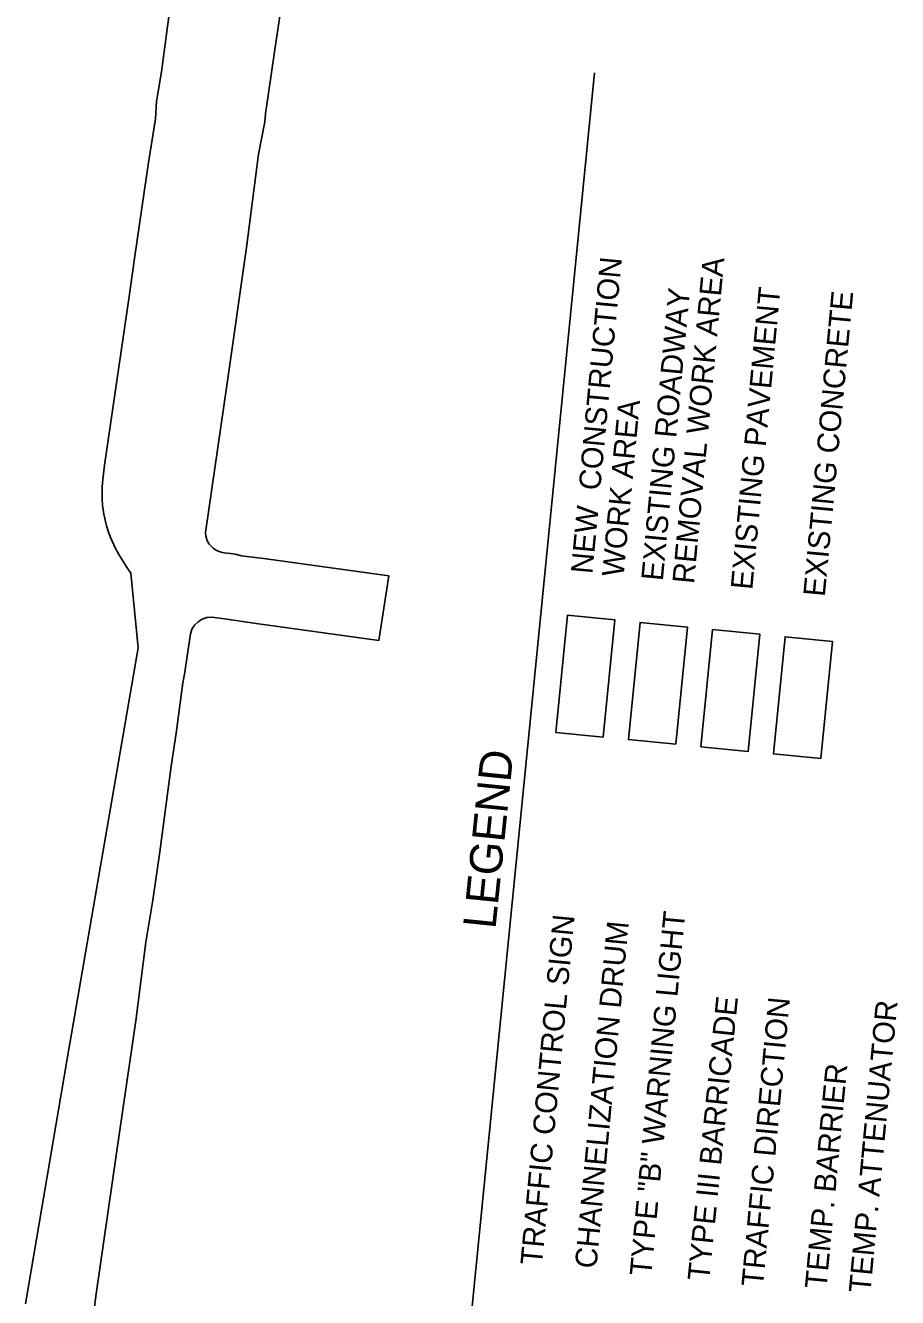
# Model space of a CAD drawing. Extents: x 1795987 to 1799689, y 243690 to 251545.
# Drawn here: x 1797696 to 1798009.1, y 245992.6 to 246449.6 of the extents above; entities that cross this region are included whole.
import ezdxf

# ---------------------------------------------------------------- set-up
doc = ezdxf.new("R2010")
doc.units = 0
doc.layers.add('LEGEND', color=7, linetype='Continuous')
doc.layers.add('Level 62', color=7, linetype='Continuous')

msp = doc.modelspace()

# ---------------------------------------------------------------- linework, layer by layer
at = {"layer": 'LEGEND'}
msp.add_line((1797853.4, 245958.82), (1797900.34, 246432.57), dxfattribs=at)
for points in [[(1797903.46, 246193.96), (1797907.63, 246236.03), (1797890.65, 246237.71), (1797886.48, 246195.64)], [(1797929.5, 246191.38), (1797933.67, 246233.45), (1797916.68, 246235.13), (1797912.51, 246193.06)], [(1797955.54, 246188.8), (1797959.71, 246230.87), (1797942.72, 246232.55), (1797938.55, 246190.48)], [(1797981.58, 246186.22), (1797985.74, 246228.29), (1797968.76, 246229.97), (1797964.59, 246187.9)]]:
    msp.add_lwpolyline(points, close=True, dxfattribs=at)
at = {"layer": 'Level 62'}
msp.add_line((1797826.51, 246251.82), (1797822.87, 246228.68), dxfattribs=at)
for points in [[(1797719.43, 245978.94), (1797721.41, 245993.91), (1797728.54, 246043.6), (1797730.99, 246060.2), (1797735.63, 246091.99), (1797739.24, 246120.33), (1797741.69, 246135.32), (1797744.16, 246152.76), (1797748.27, 246183.48), (1797750.08, 246195.31), (1797752.47, 246213.38), (1797753.02, 246216.51), (1797755.18, 246231), (1797755.75, 246232.66), (1797756.69, 246234.15), (1797757.94, 246235.38), (1797759.44, 246236.31), (1797761.1, 246236.87), (1797762.85, 246237.05), (1797767.42, 246236.38), (1797778.78, 246234.79), (1797822.87, 246228.68), (1797826.51, 246251.82), (1797782.39, 246257.94), (1797773.6, 246259.09), (1797771.33, 246259.63), (1797769.55, 246259.9), (1797767.29, 246260.12), (1797766.19, 246260.36), (1797764.62, 246261.01), (1797763.34, 246261.86), (1797761.99, 246263.23), (1797761.22, 246264.46), (1797760.7, 246266.2), (1797760.65, 246267.37), (1797768.4, 246321.08), (1797775.39, 246369.77), (1797779.65, 246403.28), (1797781.87, 246414.95), (1797782.15, 246417.96), (1797783.16, 246424.45), (1797785.46, 246440.9), (1797790.89, 246476.94)], [(1797750.05, 246471.73), (1797746.95, 246449.21), (1797744.84, 246432.9), (1797743.57, 246425.8), (1797743.06, 246422.22), (1797742.71, 246416.04), (1797740.14, 246400.35), (1797735.26, 246366.63), (1797733.04, 246351.32), (1797724.36, 246291.61), (1797723.7, 246286.42), (1797723.5, 246283.83), (1797723.5, 246279.46), (1797723.66, 246277.27), (1797724.11, 246274.01), (1797725.08, 246269.86), (1797725.95, 246267.16), (1797726.63, 246265.39), (1797728.2, 246261.97), (1797729.54, 246259.49), (1797732.54, 246254.68), (1797733.79, 246252.78), (1797736.44, 246225.98), (1797725.89, 246164.94), (1797710.86, 246077.61), (1797695.96, 245990.33)], [(1797938.55, 246190.48), (1797955.54, 246188.8), (1797959.71, 246230.87), (1797942.72, 246232.55), (1797938.55, 246190.48)]]:
    msp.add_lwpolyline(points, dxfattribs=at)

# ---------------------------------------------------------------- texts
at = {"layer": 'LEGEND'}
for s, height, rotation, p in [('NEW  CONSTRUCTION', 7.7999, 84.6544, (1797899.55, 246252.36)), ('REMOVAL WORK AREA', 7.7999, 84.6544, (1797936.03, 246248.8)), ('EXISTING ROADWAY', 7.7999, 84.6544, (1797924.84, 246249.85)), ('EXISTING PAVEMENT', 7.7999, 84.6544, (1797956.97, 246246.68)), ('EXISTING CONCRETE', 7.7999, 84.6544, (1797983.01, 246244.18)), ('WORK AREA', 7.8, 84.6544, (1797910.74, 246251.31)), ('LEGEND', 11.7, 84.1754, (1797864.73, 246124.76)), ('TYPE "B" WARNING LIGHT', 7.7999, 84.6544, (1797920.69, 246000.14)), ('TRAFFIC CONTROL SIGN', 7.7999, 84.6544, (1797881.44, 246004.04)), ('CHANNELIZATION DRUM', 7.7999, 84.6544, (1797900.99, 246002.84)), ('TYPE III BARRICADE', 7.7999, 84.1754, (1797941.47, 245998.38)), ('TRAFFIC DIRECTION', 7.7999, 84.6544, (1797960.83, 245996.3)), ('TEMP. ATTENUATOR', 7.7999, 84.6544, (1797999.37, 245994.03)), ('TEMP. BARRIER', 7.7999, 84.6544, (1797983.6, 245995.54))]:
    msp.add_text(s, height=height, rotation=rotation, dxfattribs=at).set_placement(p)

doc.saveas('drawing.dxf')
